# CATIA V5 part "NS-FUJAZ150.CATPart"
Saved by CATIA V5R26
Part number: NS-FUJAZ150
Bounding box of the stored display mesh (mm): x -60 to 120, y 0 to 198, z -60 to 60
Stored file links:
  R:\Document\坂尻\その他\ナベヤデータ変換\安全カバーキャスター\MCBJSAZ150\NS-FUJAZ150.CATPart
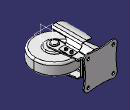
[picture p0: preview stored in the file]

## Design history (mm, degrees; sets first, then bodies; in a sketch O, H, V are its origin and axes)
Body1 (main body)
  Solid1: solid without history
  Body2
    Solid2: solid without history
  Assemble1: tool Body2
